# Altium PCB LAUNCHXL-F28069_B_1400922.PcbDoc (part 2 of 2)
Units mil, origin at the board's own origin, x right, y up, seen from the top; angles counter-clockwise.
Board outline 5140 x 2010 mil, 4 copper layers (Top, GND, VDD, Bottom), stack 60.63 mil thick; 212 components, 173 nets, 714 pads, 424 vias.
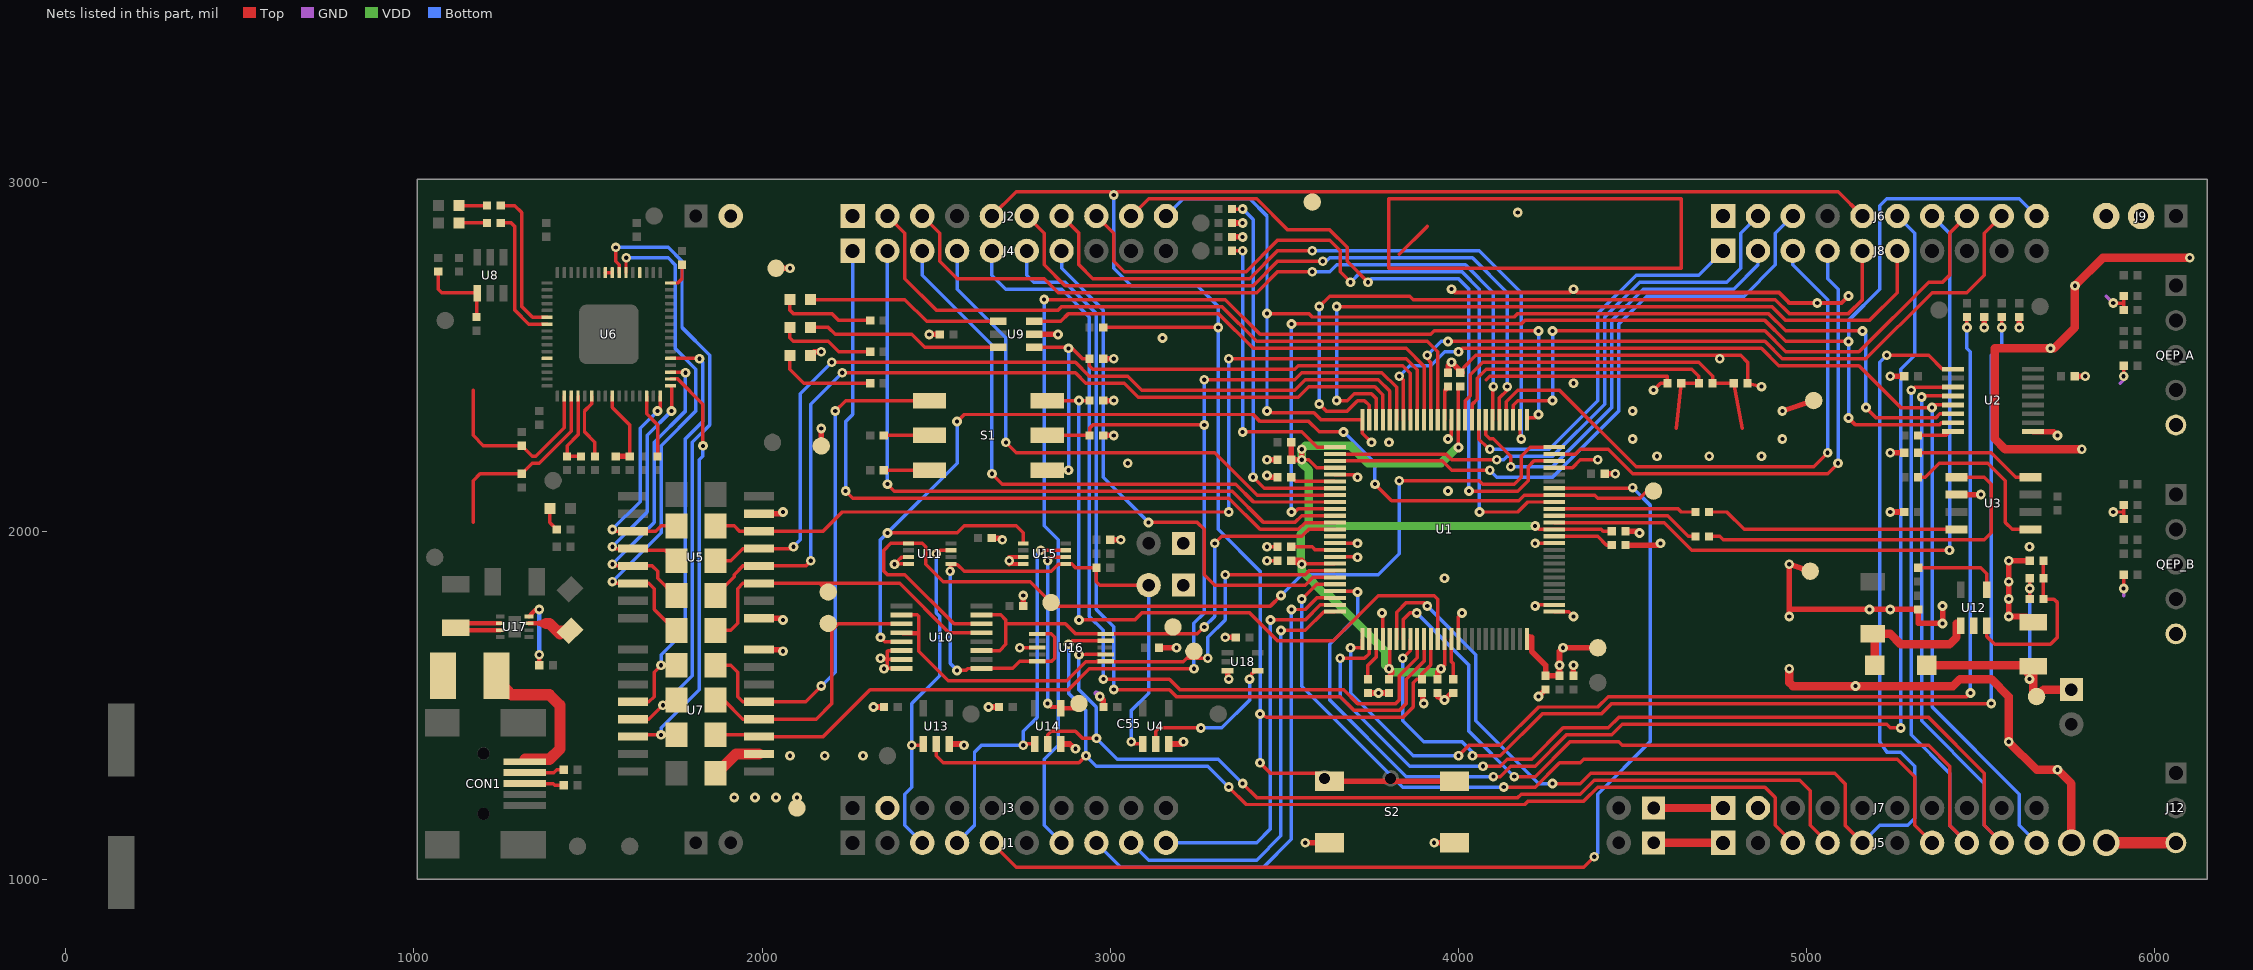
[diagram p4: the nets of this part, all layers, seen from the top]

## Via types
v1: diameter 28/28/28/28 (per signal layer), hole 12, Top to Bottom, 422 vias
v2: diameter 76.77/67.18/67.18/76.77 (per signal layer), hole 51.18, Top to Bottom, 2 vias

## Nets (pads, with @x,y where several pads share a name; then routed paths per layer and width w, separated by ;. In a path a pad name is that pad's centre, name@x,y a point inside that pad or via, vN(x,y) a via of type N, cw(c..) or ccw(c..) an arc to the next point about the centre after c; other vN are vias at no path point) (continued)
GND: C1.2 C2.2 C3.2 C4.2 C5.2 C6.2 C7.2 C8.2 C9.2 C19.2 C20.2 C21.2 C22.2 C23.2 C24.2 C26.2 C27.2 C28.2 C29.2 C30.2 C31.2 C32.2 C33.2 C34.2 C35.2 C36.2 C37.2 C38.2 C39.2 C40.2 C41.1 C42.2 C46.2 C47.2 C48.2 C49.2 C50.2 C51.2 C52.2 C53.2 C54.2 C55.2@5910.31,1875 D1.C J2.1 J3.2 J6.1 J7.2 J9.2 J9.3 JP2.2 JP6.1 JP7.1 QEP_A.5 QEP_B.5 R8.1 R9.1 R10.1 R25.2 R42.2 R45.2 S2.P$1 S2.P$2 TP20.TP TP21.TP TP22.TP TP23.TP TP24.TP U1.4 U1.15 U1.26 U1.27 U1.36 U1.47 U1.62 U1.80 U1.90 U1.92 U2.P$9 U3.P$2 U4.3 U5.9 U5.15 U7.2 U7.8 U9.2 U10.P$6 U10.P$7 U10.P$8 U11.P$3 U11.P$4 U12.2 U13.3 U14.3 U15.P$3 U15.P$4 U16.P$3 U18.3 | length 10150.3
  Top w10: v1(2340,1635) 2343.54,1631.46 2360,1631.46 ; v1(2350,1605) 2350.87,1605.87 v1@2360,1605.87 ; v1(2380,1905) v1@2390,1905.86 ; U10.P$8@2400,1605.87 v1@2360.87,1605.87 ; U10.P$7@2400,1631.46 2360,1631.46 ; U10.P$6@2400,1657.05 2362.05,1657.05 2360,1655 2360,1631.46 ; U11.P$4@2420,1905.94 2400.94,1905.94 ; U11.P$3@2420,1925.63 2400.63,1925.63 2390,1915 v1@2390,1905.86 ; v1(2710,1915) 2710.94,1914.06 v1@2710.94,1905.94 ; v1(2740,1665) 2740.63,1665.63 U16.P$3@2790,1665.63 ; v1(3450,1915) C30.2@3480.31,1915 ; v1(3450,1955) C6.2@3480.31,1955 ; U1.92@3645.04,1926.26 3708.74,1926.26 v1(3710,1925) ; U1.90@3645.04,1965.63 3709.37,1965.63 v1(3710,1965) ; U1.80@3645.04,2162.48 3702.52,2162.48 v1(3710,2155) ; v1(3780,1765) 3782.83,1762.17 U1.4@3782.83,1690.04 ; v1(3970,2265) 3979.69,2274.69 U1.62@3979.69,2319.96 ; v1(3980,2695) 3990,2685 ; U1.15@3999.37,1690.04 3999.37,1754.37 v1(4010,1765) ; C28.2@4005,2454.69 4015,2470 4050,2505 4810,2505 4830,2485 4830,2425 v1(4870,2415) ; 4080,2435 4090,2445 4600,2445 4600,2425.31 C4.2@4600.31,2425 4580,2425 v1(4560,2405) ; v1(4220,1785) 4223.46,1788.46 U1.27@4274.96,1788.46 ; v1(4220,1965) 4220.63,1965.63 U1.36@4274.96,1965.63 ; U1.26@4274.96,1768.78 4316.22,1768.78 v1(4330,1755) ; U1.47@4274.96,2182.17 4327.17,2182.17 4350,2205 v1(4400,2205) ; v1(5880,2055) 5910,2055 5910.32,2054.69 ; v1(5880,2655) 5910.32,2655 ; v1(5910,1835) 5910.32,1835.32 C55.2@5910.31,1875 ; v1(5910,2445) 5910.32,2445.31 C52.2@5910.31,2475 ; C54.2@5910.31,2035 5910.32,2054.69 ; C53.2@5910.31,2075 5910.32,2054.69 ; C51.2@5910.31,2635 5910.32,2655 ; C50.2@5910.31,2675 5910.32,2655 ; v1@2360,1605.87 2360,1631.46 ; v1@2360,1605.87 v1@2360.87,1605.87 ; v1@2360,1605.87 2360,1605 v1@2360.87,1605.87 ; v1@2390,1905.86 2390,1905 2400.94,1905.94 ; v1@2390,1905.86 2390.94,1905.94 2400.94,1905.94
  Top w12: U15.P$4@2750,1905.94 2710.94,1905.94 2710,1905 v1(2710,1915) 2710,1925 2710.63,1925.63 U15.P$3@2750,1925.63 ; 3990,2685 4320,2685 v1(4330,2695) 4340,2685 4920,2685 4950,2655 v1(5030,2655) 5100,2655 v1(5120,2675)
  Top w16: U7.8@1991.1,1660 2055,1660 v1(2060,1655) ; U5.9@1991.1,1750 2055,1750 v1(2060,1745) ; U5.15@1991.1,2050 2055,2050 v1(2060,2055) ; TP22.TP@2040,2755 v1(2080,2755) ; TP21.TP@2100,1205 v1(2100,1235) ; D1.C@2139.53,2505 2140,2505 2150,2515 v1(2170,2515) ; TP20.TP@2170,2245 v1(2170,2295) ; v1(2320,1495) C46.2@2350.31,1495 ; v1(2480,2565) C24.2@2510.31,2565 ; U13.3@2537.4,1388.82 2576.18,1388.82 v1(2580,1385) ; v1(2650,1495) C47.2@2680.31,1495 ; C48.2@2659.69,1980 2685,1980 v1(2690,1975) ; C38.2@2749.69,1785 2749.69,1814.69 v1(2750,1815) ; U9.2@2781.18,2565 v1(2850,2565) ; U14.3@2857.4,1388.82 2883.82,1388.82 v1(2900,1375) ; v1(2970,1525) 2980.32,1514.69 C7.2@2980.31,1495 ; R9.1@2979.69,2275 2999.69,2275.31 v1(3010,2275) ; R10.1@2979.69,2375 3009.69,2375.31 v1(3010,2375) ; R8.1@2979.69,2495 v1(3010,2495) ; C49.2@2999.69,1975 v1(3030,1975) ; C42.2@3139.69,1665 v1(3190,1665) ; U4.3@3167.4,1388.82 3203.82,1388.82 v1(3210,1395) ; v1(3330,1695) 3350.32,1695.32 C9.2@3360.31,1695 ; U18.3@3336.69,1599.41 3336.69,1578.31 v1(3340,1575) ; C33.2@3349.69,2845 v1(3380,2845) ; C36.2@3349.69,2885 v1(3380,2885) ; v1(3450,2160) 3450,2155 C5.2@3480.31,2155 ; v1(3450,2205) C29.2@3480.31,2205 ; v1(3560,1105) S2.P$1@3630,1105 ; C1.2@3740,1535.31 C20.2@3799.69,1535.32 ; v1(3770,1535) C20.2@3799.69,1535.32 ; C20.2@3800,1535.31 C20.2@3799.69,1535.32 ; C39.2@3895,1535.31 v1(3900,1505) ; v1(3930,1105) S2.P$2@3989,1105 ; C26.2@3940,1535.31 3940,1525 v1(3960,1515) 3980,1535 C2.2@3985,1535.31 ; C23.2@3970,2454.69 3970,2475 v1(3980,2485) 4005,2460 C28.2@4005,2454.69 4009.69,2454.69 C28.2@4010,2455 ; v1(4230,1525) C19.2@4250,1545.31 ; C21.2@4330,1584.69 v1(4330,1615) ; C40.2@4419.69,2165 v1(4450,2165) ; C22.2@4479.69,1960 4575,1960 v1(4580,1965) ; C27.2@4479.69,2000 4515,2000 v1(4520,1995) ; v1(4930,2345) TP24.TP@5020,2375 ; v1(4950,1755) 4950,1775 ; TP23.TP@5010,1885 v1(4950,1905) 4950,1775 ; v1(5240,2055) C37.2@5280.31,2055 ; v1(5240,2225) R42.2@5280.31,2225 ; v1(5240,2445) C31.2@5280.31,2445 ; v1(5390,1785) v1(5390,1735) 5320,1735 C8.2@5320,1775.31 5099.69,1775.32 4950,1775 ; U3.P$2@5430,2105 v1(5500,2105) ; v1(5510,2585) C34.2@5510,2615.31 ; v1(5610,2585) C35.2@5610,2615.31 ; R45.2@5640.31,1915 v1(5580,1915) v1(5580,1855) v1(5580,1805) v1(5580,1755) 5630,1755 C41.1@5650,1735 ; U2.P$9@5650.32,2285.87 5709.13,2285.87 v1(5720,2275) ; C32.2@5769.69,2445 v1(5800,2445)
  Top w24: v1(4950,1605) 4950,1565 4960,1555 v1(5140,1555) 5420,1555 5440,1575 5530,1575 5580,1525 v1(5580,1395) 5660,1315 v1(5720,1315) 5760,1275 v2(5760,1105) ; v1(5790,2235) 5570,2235 5540,2265 5540,2525 v1(5700,2525) 5710,2525 5770,2585 v1(5770,2705) 5850,2785 v1(6100,2785)
  Top w32: R25.2@1865.98,1305 1870,1305 1925,1360 U7.2@1991.1,1360
  GND w10: 5860,2675 v1(5880,2655) ; v1@5880,2045 v1(5880,2055) ; 5900,2425 5910,2435 v1(5910,2445) ; 5910,1815 v1(5910,1835)
  GND w16: 2960,1535 v1(2970,1525)
  other v1: 1920,1235 1980,1235 2040,1235 2080,1355 2180,1355 2290,1355 5180,1775 5240,1775 3960,1865 5640,1955 3970,2115 3050,2195 4570,2215 4720,2215 4870,2215 3800,2255 4500,2265 4930,2265 4500,2345 4330,2425 4750,2495 3150,2555 4170,2915
GPIO0: J4.1 U1.87 | length 2157
  Top w10: v1(2240,2115) 2260,2095 3340,2095 3430,2005 3540,2005 3559.69,2024.69 U1.87@3645.04,2024.69
  Bottom w10: v1(2240,2115) 2240,2315 2260,2335 J4.1@2260,2805
GPIO1: J4.2 U1.86 | length 2008.6
  Top w10: v1(2360,2135) 2380,2115 3350,2115 3440,2025 3530,2025 3549.37,2044.37 U1.86@3645.04,2044.37
  Bottom w10: v1(2360,2135) J4.2@2360,2805
GPIO2: J4.3 U1.84 | length 1741.5
  Top w10: v1(2660,2165) 2690,2135 3360,2135 3411.26,2083.74 U1.84@3645.04,2083.74
  Bottom w10: J4.3@2460,2805 2460,2735 2660,2535 v1(2660,2165)
GPIO3: J4.4 U1.83 | length 1615.8
  Top w10: v1(2700,2255) 2730,2225 3300,2225 3421.57,2103.43 U1.83@3645.04,2103.43
  Bottom w10: J4.4@2560,2805 2560,2695 2700,2555 v1(2700,2255)
GPIO4: J4.5 U1.9 | length 2535.7
  Top w10: v1(2980,1575) 3170,1575 3200,1545 3670,1545 3710,1505 3820,1505 3830,1515 3830,1585 3881.26,1636.26 U1.9@3881.26,1690.04
  Bottom w10: J4.5@2660,2805 2660,2735 2700,2695 2860,2695 2940,2615 2940,1755 2980,1715 v1(2980,1575)
GPIO5: J4.6 U1.10 | length 2495.6
  Top w10: v1(3010,1545) 3170,1545 3190,1525 3660,1525 3700,1485 3830,1485 3850,1505 3850,1575 3900.94,1625.94 U1.10@3900.94,1690.04
  Bottom w10: J4.6@2760,2805 2760,2735 2780,2715 2870,2715 2960,2625 2960,1775 3010,1725 v1(3010,1545)
GPIO6: J8.1 U1.58 | length 1151.6
  Top w10: U1.58@4058.43,2319.96 4058.43,2263.43 4063.43,2258.43 v1(4090,2235)
  Bottom w10: v1(4090,2235) 4260,2235 4400,2375 4400,2625 4510,2735 4690,2735 J8.1@4760,2805
GPIO7: J8.2 U1.57 | length 1307.3
  Top w10: U1.57@4078.11,2319.96 4078.11,2276.89 4090,2265 4100,2265 4150,2215 v1(4150,2185)
  Bottom w10: v1(4150,2185) 4270,2185 4440,2355 4440,2605 4530,2695 4790,2695 4860,2765 J8.2@4860,2805
GPIO8: J8.3 U1.54 | length 1717.8
  Top w10: U1.54@4137.17,2319.96 4137.17,2372.17 4170,2405 4290,2405 4510,2185 5020,2185 v1(5060,2225)
  Bottom w10: J8.3@4960,2805 4960,2765 5060,2665 v1(5060,2225)
GPIO9: J8.4 U1.49 | length 1484.5
  Top w10: U1.49@4274.96,2221.54 4336.54,2221.54 4350,2235 4430,2235 4500,2165 5060,2165 v1(5090,2195)
  Bottom w10: J8.4@5060,2805 5060,2725 5090,2695 v1(5090,2195)
GPIO10: J8.5 U1.74 | length 2241
  Top w10: v1(3600,2365) 3620,2345 3680,2345 3710,2375 3730,2375 3743.46,2361.54 U1.74@3743.46,2319.96 ; v1(3600,2645) 3630,2675 3860,2675 3870,2665 4910,2665 4950,2625 5120,2625 5160,2665 J8.5@5160,2805
  Bottom w10: v1(3600,2365) v1(3600,2645)
GPIO11: J8.6 U1.73 | length 2238.5
  Top w10: v1(3650,2375) 3680,2375 3700,2395 3750,2395 3763.15,2381.85 U1.73@3763.15,2319.96 ; v1(3650,2645) 4900,2645 4940,2605 5180,2605 5260,2685 J8.6@5260,2805
  Bottom w10: v1(3650,2375) v1(3650,2645)
GPIO12: J1.5 U1.44 | length 3144.2
  Top w10: J1.5@2660,1105 2730,1035 4360,1035 v1(4390,1065) ; U1.44@4274.96,2123.11 4498.11,2123.11 v1(4500,2125)
  Bottom w10: v1(4390,1065) 4400,1075 4400,1245 4550,1395 4550,2075 v1(4500,2125)
GPIO13: J4.7 U1.95 | length 1578.5
  Top w10: v1(3110,2025) 3250,2025 3270,2005 3270,1875 3300,1845 3560,1845 3582.2,1867.2 U1.95@3645.04,1867.2
  Bottom w10: J4.7@2860,2805 2860,2755 2980,2635 2980,2155 v1(3110,2025)
GPIO14: J5.7 U1.96 | length 2507.3
  Top w10: v1(3550,1805) 3592.52,1847.52 U1.96@3645.04,1847.52 ; v1(4130,1265) 4220,1265 4290,1335 4350,1335 4360,1345 5260,1345 5310,1295 5310,1155 J5.7@5360,1105
  Bottom w10: v1(3550,1805) 3550,1555 3840,1265 v1(4130,1265)
GPIO15: TP28.TP U1.88 U10.P$11 U10.P$15 U16.P$10 | length 1451.7
  Top w10: U10.P$11@2630.32,1657.05 2682.05,1657.05 2700,1675 2700,1735 ; U10.P$15@2630.32,1759.41 2685.59,1759.41 2700,1745 2700,1735 ; TP28.TP@3180,1725 3180,1715 TP28.TP@3170,1705 ; v1(3270,1725) 3250,1705 TP28.TP@3170,1705 ; v1(3300,1965) 3320,1985 3550,1985 3570,2005 U1.88@3645.04,2005 ; 2700,1735 2701.18,1733.82 2871.18,1733.82 2900,1705 U16.P$10@2986.85,1705 TP28.TP@3170,1705
  Bottom w10: v1(3270,1725) 3300,1755 v1(3300,1965)
GPIO16: J2.6 U1.55 | length 1964.5
  Top w10: J2.6@2760,2905 2810,2855 2810,2765 2870,2705 3410,2705 3480,2775 v1(3610,2775) ; U1.55@4117.48,2319.96 4117.48,2382.48 4140,2405 v1(4140,2415)
  Bottom w10: v1(3610,2775) 3620,2775 3630,2785 4040,2785 4140,2685 v1(4140,2415)
GPIO17: J2.7 U1.52 | length 2008.7
  Top w10: J2.7@2860,2905 2910,2855 2910,2765 2950,2725 3400,2725 3480,2805 v1(3580,2805) ; U1.52@4176.54,2319.96 4176.54,2268.46 v1(4180,2265) v1@4181.54,2266.54
  Bottom w10: v1(3580,2805) 4060,2805 4180,2685 v1(4180,2265)
GPIO18: J1.7 U1.51 | length 3366.8
  Top w10: v1(2810,2665) 3330,2665 3430,2565 3920,2565 3930,2575 v1(4230,2575) ; U1.51@4200,2325 4196.22,2321.22 U1.51@4196.22,2319.96 4201.22,2324.96 4201.22,2326.22 4221.22,2326.22 v1(4230,2335)
  Bottom w10: v1(2810,2665) 2810,2015 2850,1975 2850,1385 2810,1345 2810,1155 J1.7@2860,1105 ; v1(4230,2335) v1(4230,2575)
GPIO19: J2.2 U1.64 | length 2021.2
  Top w10: J2.2@2360,2905 2410,2855 2410,2725 2500,2635 2850,2635 2860,2645 3320,2645 3420,2545 3910,2545 3940.32,2514.69 U1.64@3940.31,2319.96
GPIO20: J5.5 U1.6 U2.P$1 | length 3705.2
  Top w10: U1.6@3822.2,1690.04 3822.2,1767.2 3850,1795 3900,1795 v1(3910,1785) ; v1(4270,1275) 4350,1275 4380,1305 5080,1305 5110,1275 5110,1155 J5.5@5160,1105 ; v1(5230,2505) 5350,2505 5390,2465 U2.P$1@5420,2465
  Bottom w10: v1(3910,1785) 4050,1645 4050,1455 4230,1275 v1(4270,1275) ; J5.5@5160,1105 5210,1155 5290,1155 5310,1175 5310,1325 5270,1365 5230,1365 5210,1395 5210,2485 v1(5230,2505)
GPIO21: J5.8 U1.7 U2.P$3 | length 3738.9
  Top w10: U1.7@3841.89,1690.04 3841.89,1746.89 3860,1765 v1(3880,1765) ; v1(4160,1295) 4220,1295 4320,1395 4460,1395 4470,1385 5350,1385 5410,1325 5410,1155 J5.8@5460,1105 ; v1(5300,2405) 5311.18,2413.82 U2.P$3@5420,2413.82
  Bottom w10: v1(3880,1765) 4030,1615 4030,1425 v1(4160,1295) ; v1(5300,2405) 5300,1415 5410,1305 5410,1155 J5.8@5460,1105
GPIO22: J1.8 U1.98 | length 1420.9
  Top w10: v1(3520,1775) 3560,1775 3593.15,1808.15 U1.98@3645.04,1808.15
  Bottom w10: J1.8@2960,1105 3030,1035 3440,1035 3520,1115 v1(3520,1775)
GPIO23: J5.9 U1.2 U2.P$4 | length 3984.1
  Top w10: v1(3660,1635) 3730,1635 3743.46,1648.46 U1.2@3743.46,1690.04 ; v1(4070,1325) 4120,1325 4140,1345 4210,1345 4300,1435 4430,1435 4460,1465 5350,1465 5510,1305 5510,1155 J5.9@5560,1105 ; v1(5330,2385) 5343.23,2388.23 U2.P$4@5420,2388.23
  Bottom w10: v1(3660,1635) 3660,1525 3860,1325 v1(4070,1325) ; v1(5330,2385) 5330,1455 5510,1275 5510,1155 J5.9@5560,1105
GPIO24: J6.6 U1.97 | length 3713.9
  Top w10: U1.97@3645.04,1827.83 3707.17,1827.83 v1(3710,1825) ; v1(4100,1295) 4120,1295 4150,1325 4220,1325 4310,1415 4440,1415 4470,1445 5230,1445 5240,1435 v1(5270,1435)
  Bottom w10: v1(3710,1825) 3710,1755 3630,1675 3630,1515 3850,1295 v1(4100,1295) ; J6.6@5260,2905 5310,2855 5310,2505 5270,2465 v1(5270,1435)
GPIO25: J6.7 U1.39 | length 2148.8
  Top w10: U1.39@4274.96,2024.69 4590.32,2024.69 4670,1945 v1(5410,1945)
  Bottom w10: J6.7@5360,2905 5410,2855 v1(5410,1945)
GPIO26: J6.3 U1.78 | length 1844.2
  Top w10: U1.78@3645.04,2201.85 3953.15,2201.85 3980,2175 v1(4090,2175)
  Bottom w10: v1(4090,2175) 4110,2155 4270,2155 4460,2345 4460,2595 4540,2675 4820,2675 4910,2765 4910,2855 J6.3@4960,2905
GPIO27: J6.2 U1.77 | length 1716.8
  Top w10: U1.77@3645.04,2221.54 3963.46,2221.54 3980,2205 v1(4110,2205)
  Bottom w10: v1(4110,2205) 4130,2205 4140,2215 4270,2215 4420,2365 4420,2615 4520,2715 4770,2715 4810,2755 4810,2855 J6.2@4860,2905
GPIO28: TP9.TP U1.50 U10.P$14 U11.P$1 | length 2835.4
  Top w10: U10.P$14@2630.32,1733.82 2551.18,1733.82 2410,1875 2360,1875 2350,1885 2350,1945 2370,1965 U11.P$1@2420,1965 2460,1965 2470,1955 2470,1905 2520,1855 2770,1855 2820,1805 TP9.TP@2820,1785 ; v1(3490,1815) 3460,1785 TP9.TP@2840,1785 ; v1(3830,2145) 4060,2145 4070,2135 4160,2135 4180,2155 4180,2215 4206.22,2241.22 U1.50@4274.96,2241.22 ; TP9.TP@2820,1785 TP9.TP@2830,1795 TP9.TP@2840,1785 ; TP9.TP@2820,1785 TP9.TP@2840,1785
  Bottom w10: v1(3490,1815) 3550,1875 3770,1875 3830,1935 v1(3830,2145)
GPIO29: TP27.TP U1.43 U10.P$5 U15.P$1 | length 3377.2
  Top w10: v1(2340,1695) 2352.36,1682.64 U10.P$5@2400,1682.64 ; v1(2360,1995) 2560,1995 2580,2015 2730,2015 2750,1995 U15.P$1@2750,1965 ; v1(2560,2315) 2580,2335 3410,2335 3430,2315 3570,2315 3600,2285 v1(3670,2285) ; v1(3760,2135) 3807.56,2087.44 4172.44,2087.44 4188.43,2103.43 U1.43@4274.96,2103.43 4391.57,2103.43 4400,2095 4520,2095 4540,2115 TP27.TP@4560,2115
  Bottom w10: v1(2340,1695) 2340,1975 v1(2360,1995) 2560,2195 v1(2560,2315) ; v1(3670,2285) 3760,2195 v1(3760,2135)
GPIO30: R44.2 U1.41 | length 409.5
  Top w10: U1.41@4274.96,2064.06 4599.06,2064.06 4630,2065 4640,2055 R44.2@4680.31,2055
GPIO31: R43.2 U1.40 | length 430
  Top w10: U1.40@4274.96,2044.37 4600.63,2044.37 4660,1985 R43.2@4680.31,1985
GPIO32: J1.10 U1.99 | length 1119.6
  Top w10: v1(3460,1745) 3560,1745 3603.46,1788.46 U1.99@3645.04,1788.46
  Bottom w10: J1.10@3160,1105 3420,1105 3460,1145 v1(3460,1745)
GPIO33: J1.9 U1.100 | length 1247
  Top w10: v1(3490,1715) 3560,1715 3613.78,1768.78 U1.100@3645.04,1768.78
  Bottom w10: J1.9@3060,1105 3110,1055 3420,1055 3490,1125 v1(3490,1715)
GPIO34: R8.2 S1.1 U1.68 U9.1 | length 1674.9
  Top w10: U9.1@2781.18,2527.6 2867.4,2527.6 v1(2880,2525) 2890,2525 2920,2495 R8.2@2940.31,2495 2940,2494.69 2940,2475 2950,2465 3530,2465 3540,2475 3840,2475 3861.57,2453.43 U1.68@3861.57,2319.96 ; S1.1@2819.29,2175 v1(2880,2175)
  Bottom w10: v1(2880,2175) v1(2880,2525)
GPIO39: U1.66 U9.3 | length 1345.7
  Top w10: U9.3@2781.18,2602.4 2857.4,2602.4 2880,2625 3310,2625 3410,2525 3850,2525 3900.94,2474.06 U1.66@3900.94,2319.96
GPIO40: R36.1 U1.82 | length 1061
  Top w10: R36.1@3349.69,2925 v1(3380,2925) ; v1(3410,2155) 3441.89,2123.11 U1.82@3645.04,2123.11
  Bottom w10: v1(3380,2925) 3410,2895 v1(3410,2155)
GPIO41: R37.1 U1.76 | length 833.5
  Top w10: R37.1@3349.69,2805 v1(3380,2805) ; v1(3380,2285) 3550,2285 3593.78,2241.22 U1.76@3645.04,2241.22
  Bottom w10: v1(3380,2285) v1(3380,2805)
GPIO42: R40.1 U1.1 | length 3200.2
  Top w10: v1(3690,1665) 3720,1665 3723.78,1668.78 U1.1@3723.78,1690.04 ; v1(4000,1355) 4030,1385 4120,1385 4230,1495 4400,1495 4430,1525 5460,1525 v1(5470,1535) ; v1(5460,2585) R40.1@5460,2615.31
  Bottom w10: v1(3690,1665) 3690,1535 3870,1355 v1(4000,1355) ; v1(5460,2585) 5460,2525 5470,2515 v1(5470,1535)
GPIO43: R41.1 U1.8 | length 3166.1
  Top w10: v1(3840,1635) 3861.57,1656.57 U1.8@3861.57,1690.04 ; v1(4040,1355) 4120,1355 4240,1475 4410,1475 4440,1505 v1(5530,1505) ; v1(5560,2585) R41.1@5560,2615.31
  Bottom w10: v1(3840,1635) 3840,1455 3900,1395 4010,1395 4040,1365 v1(4040,1355) ; v1(5530,1505) 5530,2505 5560,2535 v1(5560,2585)
GPIO44: J2.3 U1.56 | length 2209.5
  Top w10: J2.3@2460,2905 2510,2855 2510,2775 2560,2725 2810,2725 2850,2685 3420,2685 3480,2745 v1(3580,2745) ; U1.56@4097.8,2319.96 4097.8,2402.8 v1(4100,2415)
  Bottom w10: v1(3580,2745) 3630,2745 3650,2765 4020,2765 4100,2685 v1(4100,2415)
GPIO50: J2.8 U1.42 | length 2235.3
  Top w10: J2.8@2960,2905 3010,2855 3010,2775 3040,2745 3390,2745 3480,2835 3630,2835 3660,2805 3660,2745 v1(3690,2715) ; v1(4060,2055) 4170,2055 4198.74,2083.74 U1.42@4274.96,2083.74
  Bottom w10: v1(3690,2715) 3720,2745 4010,2745 4060,2695 v1(4060,2055)
GPIO51: J2.9 U1.48 | length 2014.5
  Top w10: J2.9@3060,2905 3110,2955 3420,2955 3510,2865 3630,2865 3680,2815 3680,2775 v1(3740,2715) ; v1(4030,2115) 4170,2115 4200,2145 4200,2185 4216.85,2201.85 U1.48@4274.96,2201.85
  Bottom w10: v1(3740,2715) 3750,2725 4000,2725 4030,2695 v1(4030,2115)
GPIO52: J6.8 U1.53 | length 1807.2
  Top w10: U1.53@4156.85,2319.96 4156.85,2361.85 4170,2375 v1(4270,2375) ; v1(4270,2575) 4880,2575 4940,2515 5150,2515 5350,2715 5390,2715 5410,2735 5410,2855 J6.8@5460,2905
  Bottom w10: v1(4270,2375) v1(4270,2575)
GPIO53: J6.9 U1.65 | length 2116.8
  Top w10: v1(3910,2505) 3910,2495 3920.63,2484.37 U1.65@3920.63,2319.96 ; v1(3970,2545) 4880,2545 4930,2495 5170,2495 5360,2685 5460,2685 5510,2735 5510,2855 J6.9@5560,2905
  Bottom w10: v1(3910,2505) 3950,2545 v1(3970,2545)
GPIO54: J5.10 U1.69 U2.P$5 | length 3200.9
  Top w10: v1(3830,2445) 3841.89,2433.11 U1.69@3841.89,2319.96 ; v1(4000,2515) 4010,2525 4870,2525 4920,2475 5150,2475 5270,2355 v1(5360,2355) 5367.64,2362.64 U2.P$5@5420,2362.64
  Bottom w10: v1(3830,2445) 3860,2475 3920,2475 3960,2515 v1(4000,2515) ; v1(5360,2355) 5360,1495 5610,1245 5610,1155 J5.10@5660,1105
GPIO55: J2.10 U1.75 U2.P$6 | length 3480.7
  Top w10: v1(3450,2345) 3464.96,2340.04 3584.96,2340.04 3605,2320 U1.75@3723.78,2319.96 3723.78,2281.22 v1(3750,2255) ; v1(3450,2625) 3570,2625 3580,2615 4160,2615 4170,2625 4890,2625 4940,2575 v1(5160,2575) ; v1(5170,2355) 5200,2325 5370,2325 5382.05,2337.05 U2.P$6@5420,2337.05
  Bottom w10: J2.10@3160,2905 3210,2955 3400,2955 3450,2905 v1(3450,2625) v1(3450,2345) ; v1(5160,2575) 5170,2565 v1(5170,2355)
GPIO56: J6.10 U1.85 U2.P$7 | length 3735
  Top w10: v1(3520,2055) 3530,2055 3539.06,2064.06 U1.85@3645.04,2064.06 ; v1(3520,2595) 4180,2595 4190,2605 4880,2605 4940,2545 v1(5120,2545) ; v1(5120,2325) 5140,2305 5380,2305 5386.46,2311.46 U2.P$7@5420,2311.46
  Bottom w10: v1(3520,2055) v1(3520,2595) ; v1(5120,2325) v1(5120,2545) 5120,2605 5210,2695 5210,2935 5230,2955 5610,2955 J6.10@5660,2905
GPIO57: U1.89
GPIO58: TP29.TP U1.94 U10.P$2 U10.P$4 U16.P$6 | length 1812.5
  Top w10: U10.P$2@2400,1759.41 2445.59,1759.41 2450,1755 2450,1705 ; U16.P$6@2986.85,1626.26 2961.26,1626.26 2930,1625 ; TP29.TP@3240,1655 3220,1635 ; v1(3280,1635) 3220,1635 ; v1(3330,1875) 3560,1875 3571.89,1886.89 U1.94@3645.04,1886.89 ; 2450,1705 2403.23,1705 U10.P$4@2400,1708.23 2446.77,1708.23 2450,1705 ; 2450,1705 2450,1655 2535,1570 2875,1570 2930,1625 ; 2930,1625 3210,1625 3220,1635
  Bottom w10: v1(3280,1635) 3280,1695 3330,1745 v1(3330,1875)
J1.3: J1.3 U11.P$7 U13.1 | length 976.8
  Top w10: v1(2430,1385) 2458.78,1385 U13.1@2462.6,1388.82 ; v1(2500,1935) 2510.31,1945.32 U11.P$7@2542.05,1945.31
  Bottom w10: J1.3@2460,1105 2410,1155 2410,1245 2430,1265 v1(2430,1385) 2430,1505 2510,1585 2510,1755 2500,1765 v1(2500,1935)
J1.4: J1.4 U14.1 U15.P$7 | length 1115.6
  Top w10: v1(2750,1385) 2756.18,1388.82 U14.1@2782.6,1388.82 ; v1(2800,1945) 2871.73,1945 U15.P$7@2872.05,1945.31
  Bottom w10: J1.4@2560,1105 2610,1155 2610,1365 2630,1385 v1(2750,1385) 2750,1425 2790,1465 2790,1935 v1(2800,1945)
J7.3: J5.3 U13.2 U16.P$9 | length 3154.1
  Top w10: U13.2@2500,1388.82 2500,1355 2520,1335 2910,1335 v1(2930,1355) ; v1(2880,1675) 2890.32,1685.32 U16.P$9@2986.85,1685.31 ; v1(3340,1265) 3390,1215 4190,1215 4200,1225 4360,1225 4400,1265 4880,1265 4910,1235 4910,1155 J5.3@4960,1105
  Bottom w10: v1(2880,1675) 2880,1535 2930,1485 v1(2930,1355) 2960,1325 3280,1325 v1(3340,1265)
J7.4: J5.4 U14.2 U16.P$7 | length 2840.5
  Top w10: U14.2@2820,1388.82 2820,1415 2830,1425 2900,1425 2920,1405 v1(2960,1405) ; v1(2910,1645) 2929.06,1645.94 U16.P$7@2986.85,1645.94 ; v1(3380,1275) 3420,1235 4170,1235 4180,1245 4350,1245 4390,1285 4980,1285 5010,1255 5010,1155 J5.4@5060,1105
  Bottom w10: v1(2910,1645) 2910,1545 2960,1495 v1(2960,1405) 3020,1345 3310,1345 v1(3380,1275)
JTAG_TRST: R28.2 S1.4 U7.5 | length 1496.9
  Top w10: R28.2@1865.98,1615 1910,1615 1930,1595 1930,1525 1945,1510 U7.5@1991.1,1510 2125,1510 v1(2170,1555) ; v1(2210,2345) 2240,2375 S1.4@2480.71,2375
  Bottom w10: v1(2170,1555) 2210,1595 v1(2210,2345)
LP_5V: C25.1 C41.2 D3.C JP3.1 R17.1 TP2.TP | length 993.5
  Top w10: v1@5640,1585 5650,1595 C41.2@5650,1612.01 C41.2@5650,1615 ; C25.1@5640.31,1805 v1(5640.32,1835) R17.1@5640.31,1865
  Top w16: C41.2@5642.99,1605 C41.2@5650,1612.01
  Top w24: D3.C@5344.8,1615 C41.2@5620,1615 ; JP3.1@5760,1545 5680,1545 TP2.TP@5660,1525 5650,1532.01 C41.2@5650,1612.01 5650,1585 v1(5640,1575) 5640,1585 C41.2@5620,1615 ; C41.2@5620,1615 5640,1605 5650,1615 C41.2@5620,1615
  Bottom w10: v1(5640,1575) 5640,1825.32 v1(5640.32,1835)
MUX_SEL: JP7.2 R11.2 U4.1 U10.P$9 U11.P$5 U15.P$5 U16.P$1 U16.P$5 | length 1883.3
  Top w10: U11.P$5@2542.05,1905.94 2542.05,1887.05 v1(2540,1885) 2540,1903.9 2561.1,1903.9 2580,1885 2830,1885 2850,1905 2871.1,1905 U15.P$5@2872.05,1905.94 2889.06,1905.94 2900,1895 2960,1895 2960,1855 2970,1845 JP7.2@3110,1845 ; v1(2560,1600) 2585.87,1600.87 2590,1605 U10.P$9@2630.32,1605.87 2719.61,1605.87 2740,1626.26 U16.P$5@2790,1626.26 2831.26,1626.26 2840,1635 2840,1695 2830,1705 U16.P$1@2790,1705 ; v1(3060,1395) 3066.18,1388.82 U4.1@3092.6,1388.82
  Top w16: R11.2@2960,1895 R11.2@2960.31,1895
  Bottom w10: v1(2540,1885) 2540,1620 v1(2560,1600) ; v1(3060,1395) 3060,1485 3110,1535 JP7.2@3110,1845
N$1: R20.1 U5.3 U6.P$16 | length 632.1
  Top w10: v1(1570,2005) 1575,2000 U5.3@1628.9,2000 1695,2000 1710,2015 R20.1@1754.02,2015 ; v1(1700,2345) 1707.64,2352.64 U6.P$16@1707.64,2387.83
  Bottom w10: v1(1570,2005) 1650,2085 1650,2295 v1(1700,2345)
N$2: C17.1 U6.P$2 | length 541.7
  Top w10: 1170,2405 1170,2275 1199.69,2245.31 C17.1@1310,2245.31 1340.32,2215 1350,2215 1432.05,2297.05 U6.P$2@1432.05,2387.83
N$3: 
N$4: R19.1 U5.4 U6.P$17 | length 740.3
  Top w10: v1(1570,1955) 1575,1950 U5.4@1628.9,1950 1628.9,1953.9 1630,1955 1640,1945 1720,1945 1750,1915 R19.1@1754.02,1915 ; U6.P$17@1737.17,2417.36 1740,2410.2 v1(1740,2345)
  Bottom w10: v1(1570,1955) 1670,2055 1670,2275 v1(1740,2345)
N$5: R32.1 U6.P$18 U7.14 | length 1293.6
  Top w10: U7.14@1628.9,1410 1633.9,1415 R32.1@1754.02,1415 v1(1710,1415) ; U6.P$18@1737.17,2437.05 1757.95,2437.05 1830,2365 v1(1830,2245)
  Bottom w10: v1(1710,1415) 1710,1435 1820,1545 1820,2205 1830,2215 v1(1830,2245)
N$6: R18.1 U5.5 U6.P$19 | length 913.5
  Top w10: v1(1570,1905) 1575,1900 U5.5@1628.9,1900 1685,1900 1700,1885 1700,1865 1750,1815 R18.1@1754.02,1815 ; U6.P$19@1737.17,2456.73 1778.27,2456.73 v1(1780,2455)
  Bottom w10: v1(1570,1905) 1690,2025 1690,2255 1780,2345 v1(1780,2455)
N$7: C18.1 U6.P$3 | length 561.8
  Top w10: 1170,2025 1170,2145 1190,2165 1309.69,2165 C18.1@1310,2164.69 1340.32,2195 1360,2195 1451.73,2286.73 U6.P$3@1451.73,2387.83
N$8: C3.1 R7.2 U1.60 | length 1076.3
  Top w10: U1.60@4019.06,2319.96 4019.06,2374.06 4034.06,2389.06 4034.06,2449.06 4070,2485 4690,2485 4730,2445 4730,2445.31 R7.2@4729.69,2425 C3.1@4790.31,2425 4815,2295
N$9: R4.1 S1.6 | length 131
  Top w10: R4.1@2349.69,2175 S1.6@2480.71,2175
N$10: R5.1 S1.5 | length 131
  Top w10: R5.1@2349.69,2275 S1.5@2480.71,2275
N$11: C4.1 R7.1 U1.59 | length 981.9
  Top w10: U1.59@4038.74,2319.96 4038.74,2363.74 4053.74,2378.74 4053.74,2438.74 4080,2465 4670,2465 4690,2445 R7.1@4690,2425 ; 4625,2295 C4.1@4639.69,2425 R7.1@4690,2425 ; R7.1@4690.31,2425 R7.1@4690,2425
N$12: R12.2 R31.1 U8.1 | length 237.8
  Top w10: R12.2@1070,2745.31 1070,2695 1080,2685 1181.42,2685 U8.1@1182.6,2683.82 1180,2681.22 R31.1@1180,2614.69
N$13: R28.1 U6.P$21 U7.12 | length 1226.8
  Top w10: U7.12@1628.9,1510 1675,1510 1690,1525 1690,1595 v1(1710,1615) R28.1@1754.02,1615 ; U6.P$21@1737.17,2496.1 1818.9,2496.1 v1(1820,2495)
  Bottom w10: v1(1710,1615) 1710,1645 1780,1715 1780,2265 1830,2315 1830,2485 v1(1820,2495)
N$14: R23.1 U6.P$32 | length 78.3
  Top w10: U6.P$32@1737.17,2712.64 1757.64,2712.64 1770,2725 R23.1@1770,2765.31
N$15: U6.P$40 U6.P$41 | length 19.7
  Top w10: U6.P$41@1550.16,2742.17 U6.P$40@1569.84,2742.17
N$16: R16.1 U5.6 U6.P$38 | length 1502.6
  Top w10: v1(1570,1855) 1575,1850 U5.6@1628.9,1850 1675,1850 1690,1835 1690,1775 1740,1725 1750,1715 R16.1@1754.02,1715 ; U6.P$38@1609.21,2742.17 1609.21,2774.21 v1(1610,2785)
  Bottom w10: v1(1570,1855) 1710,1995 1710,2245 1810,2345 1810,2465 1750,2525 1750,2765 1730,2785 v1(1610,2785)
N$17: R24.2 U6.P$6 | length 194.2
  Top w10: U6.P$6@1510.79,2387.83 1510.79,2365.79 1490,2345 1490,2285 1520,2255 R24.2@1520,2215
  Top w16: R24.2@1520,2214.69 R24.2@1520,2215
N$18: J12.3 | length 200
  Top w32: v2(5860,1105) J12.3@6060,1105
N$19: R26.1 U6.P$54 | length 424.2
  Top w10: R26.1@1249.69,2935 1290,2935 1310,2915 1310,2645 1340.79,2614.21 U6.P$54@1382.83,2614.21
N$20: C11.1 L1.2 U6.P$4 | length 226.2
  Top w10: C11.1@1440,2214.69 L1.2@1480,2214.69 ; C11.1@1440,2215 1440,2245 1471.42,2276.42 U6.P$4@1471.42,2387.83
  Top w16: C11.1@1440,2214.69 C11.1@1440,2215
N$21: R30.1 U6.P$39 U7.13 | length 1833.2
  Top w10: v1(1580,2815) 1580,2775 1589.53,2764.53 U6.P$39@1589.53,2742.17 ; U7.13@1628.9,1460 1675,1460 v1(1715,1500) v1@1720,1505 ; v1@1720,1505 1744.02,1505 R30.1@1754.02,1515 1730,1515 v1@1720,1505
  Bottom w10: v1(1580,2815) 1730,2815 1770,2775 1770,2585 1850,2505 1850,2305 1800,2255 1800,1585 v1(1715,1500)
N$22: R27.1 U6.P$55 | length 394
  Top w10: R27.1@1249.69,2885 1280,2885 1290,2875 1290,2635 1330.47,2594.53 U6.P$55@1382.83,2594.53
N$23: D7.C R26.2 | length 80.8
  Top w10: D7.C@1129.53,2935 R26.2@1210.31,2935
N$24: D8.C R27.2 | length 80.8
  Top w10: D8.C@1129.53,2885 R27.2@1210.31,2885
N$25: J7.1 JP5.1 | length 200
  Top w24: JP5.1@4560,1205 J7.1@4760,1205
N$26: C10.1 L2.2 U6.P$9 | length 314
  Top w10: U6.P$9@1569.84,2387.83 1569.84,2355.16 1620,2305 1620,2215 C10.1@1620,2214.69 1580.32,2214.69 L2.2@1580,2215
  Top w16: L2.2@1580,2214.69 1580.32,2215 1620,2215 1619.69,2214.69 L2.2@1580.32,2214.69
N$27: D1.A R1.1 | length 287.1
  Top w10: D1.A@2080.47,2505 2080,2504.53 2080,2465 2120,2425 R1.1@2310.31,2425
N$28: C1.1 U1.3 | length 124.9
  Top w10: C1.1@3740,1574.69 3740,1615 3763.15,1638.15 U1.3@3763.15,1690.04
N$29: C2.1 U1.14 | length 117.5
  Top w10: U1.14@3979.69,1690.04 3979.69,1625.32 3985,1620 C2.1@3985,1574.69
N$30: C22.1 U1.37 | length 175.9
  Top w10: U1.37@4274.96,1985.31 4399.69,1985.32 4425,1960 C22.1@4440.31,1960
N$31: C23.1 U1.63 | length 111.9
  Top w10: U1.63@3960,2319.96 3960,2405.31 C23.1@3970,2415.31 3970,2410 C23.1@3965,2405
N$32: J5.1 JP4.1 | length 200
  Top w24: JP4.1@4560,1105 J5.1@4760,1105
N$33: R2.2 U2.P$8 | length 106.2
  Top w10: R2.2@5319.69,2275 5400,2275 5410,2285 5409.13,2285 U2.P$8@5420,2285.87
N$34: R22.2 U6.P$14 | length 186.3
  Top w10: U6.P$14@1668.27,2387.83 1668.27,2336.73 1700,2305 R22.2@1700,2214.69
N$35: C5.1 U1.81 | length 140.6
  Top w10: C5.1@3526.89,2147.8 C5.1@3519.69,2155 3531.89,2142.8 U1.81@3645.04,2142.8
N$36: C6.1 U1.91 | length 134.8
  Top w10: C6.1@3523.74,1950.94 C6.1@3519.69,1955 3580,1955 3589.06,1945.94 U1.91@3645.04,1945.94
N$37: 
N$38: CON1.2 R15.1 | length 115.7
  Top w10: CON1.2@1318.11,1306.5 1401.5,1306.5 1410,1315 R15.1@1430.31,1315
N$39: CON1.3 R33.1 | length 114.3
  Top w10: CON1.3@1318.11,1275 1400,1275 1405,1270 R33.1@1430.31,1270
N$40: D4.A R46.1 | length 68.3
  Top w10: D4.A@1390.47,2065 1390.32,2024.84 R46.1@1410.31,2005
N$41: 
N$42: U4.2 U18.4 | length 439.8
  Top w10: U4.2@3130,1388.82 3130,1425 3140,1435 v1(3260,1435) ; v1(3400,1575) 3405.59,1590.59 U18.4@3423.31,1599.41
  Bottom w10: v1(3260,1435) 3320,1435 3400,1515 v1(3400,1575)
N$43: R47.2 U17.P$8 | length 197.8
  Top w12: U17.P$8@1330.71,1755 1340,1764.29 1350,1775 v1(1360,1775) ; v1(1360,1645) 1360.32,1634.69 R47.2@1360.31,1615
  Bottom w12: v1(1360,1645) v1(1360,1775)
N$44: R35.1 U3.P$5 | length 488.5
  Top w10: R35.1@5319.69,2155 5340,2155 5380,2195 5520,2195 5570,2145 5570,2025 5590,2005 U3.P$5@5642.6,2005
N$45: R42.1 U3.P$8 | length 351.9
  Top w10: R42.1@5319.69,2225 5530,2225 5600,2155 U3.P$8@5642.6,2155
N$46: R43.1 U3.P$1 | length 1071
  Top w10: R43.1@4719.69,1985 4750,1985 4760,1975 5510,1975 5530,1995 5530,2135 5510,2155 U3.P$1@5430,2155
N$47: D9.C U9.6 | length 563.1
  Top w10: D9.C@2139.53,2585 2190,2585 2210,2565 2430,2565 2467.4,2527.6 U9.6@2678.82,2527.6
N$48: R44.1 U3.P$4 | length 731
  Top w10: R44.1@4719.69,2055 4770,2055 4820,2005 U3.P$4@5430,2005
N$49: D9.A R38.1 | length 277.1
  Top w10: D9.A@2080.47,2585 2080,2584.53 2080,2555 2090,2545 2190,2545 2220,2515 R38.1@2310.31,2515
N$50: D10.A R39.1 | length 273.2
  Top w10: D10.A@2080.47,2665 2080,2665 2080,2635 2090,2625 2200,2625 2220,2605 R39.1@2310.31,2605
N$51: L7.P$2 U17.P$7 | length 138.9
  Top w12: U17.P$7@1330.71,1735.31 1359.69,1735.32 1360,1735
  Top w16: 1359.69,1735.32 1370,1735
  Top w24: 1370,1735 1380,1735
  Top w32: 1380,1735 1390,1735 1420,1705 1420,1713.54 L7.P$2@1448.18,1713.54
N$53: R14.2 U12.4 | length 250.7
  Top w10: R14.2@5320,1894.69 5500,1894.69 5517.4,1877.28 U12.4@5517.4,1831.18
N$55: D3.A L6.P$2 U12.1 | length 408
  Top w16: 5430,1735 5436.18,1728.82 U12.1@5442.6,1728.82
  Top w24: D3.A@5195.2,1615 5195.2,1699.8 L6.P$2@5190,1705 5240,1705 5270,1675 5410,1675 5430,1695 5430,1735
N$56: C25.2 R17.2 R45.1 U12.3 | length 505.9
  Top w10: U12.3@5517.4,1728.82 5517.4,1697.6 5540,1675 5700,1675 5720,1695 5720,1795 5710,1805 C25.2@5679.69,1805 R17.2@5679.69,1865 R45.1@5679.69,1915
N$57: 
N$58: 
N$59: D10.C U9.4 | length 565.2
  Top w10: D10.C@2139.53,2665 2410,2665 2472.6,2602.4 U9.4@2678.82,2602.4
OCTW_O: TP4.TP U14.4 U15.P$6 | length 587.5
  Top w10: v1(2820,1915) 2829.37,1925.63 U15.P$6@2872.05,1925.63 ; U14.4@2857.4,1487.6 U14.4@2857.4,1491.18
  Top w12: v1(2820,1505) 2830,1495 2853.58,1495 U14.4@2857.4,1491.18 2916.18,1491.18 TP4.TP@2910,1505
  Bottom w10: v1(2820,1505) v1(2820,1915)
PWREN#: U6.P$60
RESET#: C39.1 J2.5 J6.5 R6.1 S2.P$3 S2.P$4 TP18.TP U1.11 | length 6146.7
  Top w10: J2.5@2660,2905 2730,2975 3000,2975 v1(3010,2965) 3020,2975 3580,2975 ; R6.1@2979.69,2585 v1(3310,2585) ; v1(3430,1335) 3440,1325 3460,1305 3600,1305 3613,1282 S2.P$3@3630,1282 ; v1(3430,1475) 3450,1465 3840,1465 3870,1495 3870,1565 3880,1575 3880.32,1574.69 C39.1@3895,1574.69 3895,1590 3920.63,1615.63 U1.11@3920.63,1690.04 ; TP18.TP@3580,2945 3580,2975 ; J6.5@5160,2905 5090,2975 3580,2975
  Top w16: S2.P$3@3630,1282 S2.P$4@3989,1282
  Bottom w10: v1(3010,2965) 3010,2755 3060,2705 3250,2705 3310,2645 v1(3310,2585) 3310,2005 3430,1885 v1(3430,1475) ; v1(3430,1335) v1(3430,1475) ; 3430,1435 v1(3430,1475)
S$1:  | length 2080
  Top w10: 3800,2755 3800,2955 4640,2955 4640,2755 3800,2755
S$2:  | length 113.1
  Top w10: 3830,2795 3910,2875
SCI_RX: R16.2 TP25.TP U5.11 U10.P$13 | length 977.9
  Top w10: R16.2@1865.98,1715 1910,1715 1930,1735 1930,1835 1945,1850 U5.11@1991.1,1850 2180,1850 ; TP25.TP@2190,1825 2170,1845 2175,1845 2180,1850 ; U10.P$13@2630.32,1708.23 2536.77,1708.23 2395,1850 2180,1850
SCI_TX: R30.2 TP26.TP U7.4 U10.P$3 | length 814.5
  Top w10: R30.2@1865.98,1515 1890,1515 1945,1460 U7.4@1991.1,1460 2155,1460 2200,1505 2200,1715 TP26.TP@2205,1720 ; TP26.TP@2190,1735 TP26.TP@2205,1720 ; U10.P$3@2400,1733.82 2218.82,1733.82 TP26.TP@2205,1720
SUSPEND#: U6.P$36
TCK: R20.2 U1.67 U5.14 | length 2641
  Top w10: R20.2@1865.98,2015 1920,2015 1935,2000 U5.14@1991.1,2000 2175,2000 2230,2055 v1(3340,2055) ; v1(3340,2495) 3850,2495 3881.26,2463.74 U1.67@3881.26,2319.96
  Bottom w10: v1(3340,2055) v1(3340,2495)
TDI: R19.2 U1.71 U5.13 | length 2560.2
  Top w10: R19.2@1865.98,1915 1910,1915 1945,1950 U5.13@1991.1,1950 2085,1950 v1(2090,1955) ; v1(2200,2485) 2900,2485 2940,2445 3050,2445 3090,2405 3530,2405 3560,2435 3770,2435 3802.52,2402.48 U1.71@3802.52,2319.96
  Bottom w10: v1(2090,1955) 2110,1975 2110,2395 v1(2200,2485)
TDO: R9.2 R32.2 S1.2 U1.70 U7.3 | length 3445.1
  Top w10: R32.2@1865.98,1415 1986.1,1415 U7.3@1991.1,1410 2175,1410 2310,1545 2880,1545 2940,1605 v1(3240,1605) ; S1.2@2819.29,2275 R9.2@2940.31,2275 2940.32,2295.31 2950,2305 v1(3270,2305) ; v1(3270,2435) 3530,2435 3550,2455 3780,2455 3822.2,2412.8 U1.70@3822.2,2319.96
  Bottom w10: v1(3240,1605) 3240,1735 3270,1765 v1(3270,2305) v1(3270,2435)
TMS: R18.2 U1.72 U5.12 | length 2572.1
  Top w10: R18.2@1865.98,1815 1920,1869.02 1920,1875 1945,1900 U5.12@1991.1,1900 2125,1900 v1(2140,1915) ; v1(2230,2455) 2900,2455 2930,2425 3040,2425 3080,2385 3540,2385 3570,2415 3760,2415 3782.83,2392.17 U1.72@3782.83,2319.96
  Bottom w10: v1(2140,1915) 2140,2365 v1(2230,2455)
TRST: R10.2 S1.3 U1.12 | length 1995.5
  Top w10: S1.3@2819.29,2375 v1(2910,2375) R10.2@2940.31,2375 ; v1(2910,1745) 3070,1745 3090,1765 3400,1765 3480,1685 3640,1685 3770,1815 3930,1815 3940.32,1804.69 U1.12@3940.31,1690.04
  Bottom w10: v1(2910,1745) v1(2910,2375)
USBVCC: C44.2 F1.1 U17.P$2 U17.P$3 | length 263
  Top w12: C44.2@1120,1722.01 1126.38,1715.63 U17.P$3@1248.03,1715.63 ; C44.2@1120,1725 1130,1735 1140,1735 1140.32,1735.32 U17.P$2@1248.03,1735.31
VDDA: C19.1 L3.1 TP19.TP U1.25 | length 374.2
  Top w10: U1.25@4196.22,1690.04 4204.96,1690.04 4210,1685 ; 4205.04,1699.96 4210,1695
  Top w16: 4210,1695 4210,1685 4210,1655 4250,1615 C19.1@4250,1584.69 L3.1@4290,1584.69 v1(4290,1615) 4290,1655 v1(4300,1665) TP19.TP@4400,1665
VDDIO: C20.1 C26.1 C27.1 C28.1 C29.1 C30.1 L4.1 U1.5 U1.13 U1.38 U1.61 U1.79 U1.93 | length 3140.4
  Top w10: v1(3550,1905) 3551.57,1906.57 U1.93@3645.04,1906.57 ; v1(3550,2205) 3570,2205 3592.83,2182.17 U1.79@3645.04,2182.17 ; v1@3558.11,1911.57 3557.49,1912.21 3550,1920 3530,1920 C30.1@3519.69,1915 C30.1@3520,1915 ; C20.1@3800,1574.69 3800,1585 3807.52,1592.52 ; v1(3800,1605) 3802.52,1607.52 U1.5@3802.52,1690.04 ; v1(3950,1605) 3960,1615 U1.13@3960,1690.04 ; v1(4000,2240) 3999.37,2240.63 U1.61@3999.37,2319.96 3999.37,2409.69 C28.1@4005,2415.31 C28.1@4004.37,2414.69 ; v1(4220,2015) 4225.98,2009.02 4230,2005 U1.38@4274.96,2005 4410,2005 4415,2000 C27.1@4440.31,2000 ; C30.1@3520,1915 3520.15,1914.85 3525,1910 3530,1910 3527.61,1912.39 3525,1915 C30.1@3520,1915
  Top w16: C30.1@3519.69,1915 3520.15,1914.85 3527.61,1912.39 v1(3550,1905) 3536.57,1911.57 ; C29.1@3519.69,2205 L4.1@3519.69,2255 ; C29.1@3520,2205 v1(3550,2205) v1(3550,2235) ; v1(3800,1605) 3807.52,1597.48 3807.52,1592.52 ; C26.1@3940,1574.69 3940,1595 v1(3950,1605)
  VDD w16: v1@3546.57,1911.57 v1(3550,1905)
  VDD w24: v1@3546.57,1911.57 3546.57,1991.57 3570,2015 3570,2025 ; v1(3550,1905) 3550,1885 3620,1815 3630,1815 3790,1655 3790,1615 v1(3800,1605) 3810,1595 3940,1595 v1(3950,1605) ; v1(4000,2240) 3995,2240 3950,2195 3740,2195 3690,2245 3560,2245 v1(3550,2235) v1(3550,2205) 3550,2195 3570,2175 3570,2025 ; v1(4220,2015) 3580,2015 3570,2025
XUSB: CON1.1@1318.11,1337.99 F1.2 | length 482.9
  Top w10: F1.2@1236.77,1585 1236.77,1577.32 F1.2@1239.05,1575.05
  Top w16: CON1.1@1318.11,1337.99 1318.11,1343.11 CON1.1@1320,1345
  Top w32: F1.2@1230,1585 1239.05,1575.05 1280,1530 1390,1530 1420,1500 1420,1375 1390,1345 CON1.1@1320,1345
pads on no net: C55.1@160,1400 C55.1@3615,1290 C55.2@160,1020 C55.2@3805,1290 CON1.1@1200,1188.39 CON1.1@1200,1361.61 CON1.4 CON1.M1 CON1.M2 CON1.M3 CON1.M4 J2.4 J3.10 J4.8 J5.2 J5.6 J6.4 J7.10 J8.7 J8.8 U1.24 U1.45 U5.7 U6.P$22 U6.P$23 U6.P$24 U6.P$26 U6.P$27 U6.P$28 U6.P$29 U6.P$30 U6.P$33 U6.P$34 U6.P$43 U6.P$44 U6.P$45 U6.P$46 U6.P$48 U6.P$52 U6.P$53 U6.P$57 U6.P$58 U6.P$59 U7.6 U7.11 U10.P$1 U10.P$12 U16.P$2 U16.P$4 U18.1
copper on no net: | length 366.4
  Top w10: 3933.31,2830 ccw(c3875,2830) 3933.31,2830

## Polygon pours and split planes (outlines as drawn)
no net on tDocu (solid): 2645,1180 2665,1180 2665,1197.07 2697.07,1165 2665,1132.93 2665,1150 2645,1150
GND on GND "GND-GND" (solid, remove dead copper, pour order 0): 1885,2990 1885,1009.97 5855,1030.03 5855,1603.49 5872.68,1630 6122.07,1630 6135,1642.93 6135,2990
AGND on GND "GND-AGND" (solid, remove dead copper, pour order 24): 1014.96,2990 1835,2990 1835,1010 1407.93,1010 1395,1022.93 1395,1474.19 1386.4,1500 1317.93,1500 1295,1522.93 1295,1632.93 1267.93,1660 1025.04,1660
GND on Top "Top-GND" (solid, remove dead copper, pour order 2): 5085,1930 5085,1837.07 5112.07,1810 5272.07,1810 5292.07,1790 5357.93,1790 5367.93,1800 5537.93,1800 5555,1817.07 5555,1947.07 5567.93,1960 5655,1960 5655,1920 5635,1920 5635,1902.93 5622.07,1890 5612.07,1890 5605,1882.93 5605,1787.07 5622.07,1770 5695,1770 5695,1712.93 5682.07,1700 5597.93,1700 5537.93,1760 5502.07,1760 5480,1737.93 5457.93,1760 5412.07,1760 5405,1752.93 5405,1700 5287.93,1700 5237.93,1750 5132.07,1750 5105,1722.93 5105,1545 4885,1545 4885,1930
GND on Top "Top-GND 1" (solid, remove dead copper, pour order 4): 4277.93,2440 4517.93,2200 5002.07,2200 5045,2242.93 5045,2430 4932.07,2430 4852.07,2510 4697.93,2510 4747.93,2460 4807.93,2460 4825,2442.93 4825,2382.93 4865,2342.93 4865,2277.07 4837.93,2250 4612.07,2250 4575,2287.07 4575,2342.93 4605,2372.93 4605,2440
GND on Top "Top-GND 2" (solid, remove dead copper, pour order 6): 2315,1380 2027.93,1380 2015,1367.07 2015,1352.93 2037.93,1330 2077.93,1330 2095,1312.93 2095,1297.07 2067.93,1270 1942.07,1270 1925,1287.07 1925,1350 1897.93,1350 1855,1307.07 1855,1297.07 1835,1277.07 1835,1262.93 1897.93,1200 1977.93,1200 2007.93,1170 2135,1170 2135,1310 2315,1310
GND on Top "Top-GND 3" (solid, remove dead copper, pour order 8): 3695,2257.07 3695,1762.93 3727.93,1730 4211.67,1730 4255,1762.5 4255,1777.07 4235,1797.07 4235,2257.07 4202.07,2290 3727.93,2290
+3V3 on Top "Top-+3V3" (solid, remove dead copper, pour order 10): 2062.07,2310 1917.93,2310 1885,2277.07 1885,2112.93 1897.93,2100 2062.07,2100 2075,2112.93 2075,2297.07
+3V3 on Top "Top-+3V3 1" (solid, remove dead copper, pour order 12): 2200,1150 1992.07,1150 1972.07,1170 1887.93,1170 1865,1147.07 1865,1042.93 1887.93,1020 2272.07,1020 2305,1052.93 2305,1127.07 2282.07,1150
+3V3 on Top "Top-+3V3 2" (solid, remove dead copper, pour order 16): 5105,1930 5105,1852.93 5137.93,1820 5297.93,1820 5307.93,1810 5352.07,1810 5372.07,1830 5417.93,1830 5437.93,1810 5452.07,1810 5465,1822.93 5465,1870 5265,1870 5265,1930
USBVCC on Top "Top-USBVCC" (solid, remove dead copper, pour order 18): 1215,1740 1202.07,1740 1192.07,1750 1057.93,1750 1035,1727.07 1035,1522.93 1047.93,1510 1132.07,1510 1155,1532.93 1155,1652.93 1215,1712.93
AGND on Top "Top-AGND" (solid, remove dead copper, pour order 20): 1046.46,1888.54 1057.93,1900 1252.07,1900 1263.54,1888.54 1275,1877.07 1275,1807.07 1285,1797.07 1285,1772.93 1272.07,1760 1047.93,1760 1035,1772.93 1035,1877.07
AGND on Top "Top-AGND 1" (solid, remove dead copper, pour order 22): 1415,2710 1692.07,2710 1705,2697.07 1705,2522.93 1675,2492.93 1675,2467.07 1695,2447.07 1695,2420 1415,2420
FTDI_3V3 on Top "Top-FTDI_3V3" (solid, remove dead copper, pour order 26): 1425,1980 1307.93,1980 1295,1967.07 1295,1832.93 1317.93,1810 1462.07,1810 1485,1832.93 1485,1920 1425,1920
FTDI_3V3 on Top "Top-FTDI_3V3 1" (solid, remove dead copper, pour order 28): 1585,1307.07 1585,1112.93 1597.93,1100 1667.93,1100 1717.93,1050 1845,1050 1845,1195 1845,1207.07 1822.07,1230 1702.07,1230 1695,1237.07 1695,1297.07 1672.07,1320 1597.93,1320
FTDI_3V3 on Top "Top-FTDI_3V3 2" (solid, remove dead copper, pour order 32): 1725,2280 1725,2187.07 1717.93,2180 1695,2180 1695,2102.93 1707.93,2090 1785,2090 1785,2280
VDDIO on Top "Top-VDDIO" (solid, remove dead copper, pour order 36): 3515,2260 3515,2190 3585,2190 3585,2227.07 3552.07,2260
+3V3 on VDD "VDD-+3V3" (solid, remove dead copper, pour order 14): 1885,1042.93 1885,2957.07 1927.94,3000.01 3960,2990 4819.96,2990 6125,3000.04 6125,2790 5842.18,2790 5595,2523.04 5595,1360.04 4420.02,1350 3462.07,1350 3402.07,1290 3317.93,1290 3257.93,1350 2152.07,1350 2145,1342.93 2145,1157.07 2172.07,1130 2317.93,1130 2337.93,1150 3192.07,1150 3212.07,1130 3437.93,1130 3477.95,1170.02 4602.09,1159.98 4625,1137.07 4625,1020 1907.93,1020
FTDI_3V3 on VDD "VDD-FTDI_3V3" (solid, remove dead copper, pour order 30): 1035,2970 1035,1732.93 1047.93,1720 1327.93,1720 1435,1612.93 1435,1437.07 1355,1357.07 1355,1142.93 1457.93,1040 1822.07,1040 1835,1052.93 1835,2970
+5V on VDD "VDD-+5V" (solid, remove dead copper, pour order 34): 2165,1320 2165,1182.93 2197.93,1150 2302.4,1150 2342.4,1200 3187.93,1200 3237.93,1150 3402.07,1150 3452.07,1200 4608.49,1200 4635,1182.32 4635,1052.93 4657.93,1030 5815,1030 5815,2122.93 5852.07,2160 5867.93,2160 5885,2142.93 5885,1592.93 5927.93,1550 6082.07,1550 6125,1592.93 6125,2737.07 6102.07,2760 5847.8,2760 5625,2516.94 5625,1320.02 3477.94,1330.01 3417.93,1270 3312.07,1270 3262.07,1320

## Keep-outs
Bottom:
  rectangle: 1870,2525 1970,2625
Keep-Out Layer:
  the board outline again, w10

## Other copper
Top:
  text "94V-0" at 4000,2939.19 h34 r180
  text "For evaluation only;" at 4625,2898.52 h34 r180
  text "Pb" at 3915,2865.24 h42.5 r180
  text "not FCC approved" at 4625,2864.52 h34 r180
  text "for resale." at 4625,2819.19 h34 r180

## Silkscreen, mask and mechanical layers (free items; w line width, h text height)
Top Overlay:
  rectangle: 1850,2155 1890,2845
  rectangle: 1850,1165 1890,1255
  lines w6: 2910,1865 2940,1915 ; 2920,1905 2940,1915 ; 2940,1895 2940,1915
  text "20" at 2270,2955 h49.6 r90
  text "19" at 2370,2955 h49.6 r90
  text "18" at 2470,2955 h49.6 r90
  text "17" at 2580,2955 h49.6 r90
  text "16" at 2670,2955 h49.6 r90
  text "15" at 2770,2955 h49.6 r90
  text "14" at 2870,2955 h49.6 r90
  text "13" at 2970,2955 h49.6 r90
  text "12" at 3070,2955 h49.6 r90
  text "11" at 3180,2955 h49.6 r90
  text "60" at 4770,2955 h49.6 r90
  text "59" at 4870,2955 h49.6 r90
  text "58" at 4970,2955 h49.6 r90
  text "57" at 5080,2955 h49.6 r90
  text "56" at 5170,2955 h49.6 r90
  text "55" at 5270,2955 h49.6 r90
  text "54" at 5370,2955 h49.6 r90
  text "53" at 5470,2955 h49.6 r90
  text "52" at 5570,2955 h49.6 r90
  text "51" at 5680,2955 h49.6 r90
  text "Reset" at 3620,2895 h49.6
  text "3V3" at 6070,2775 h49.6 r90
  text "GND" at 5870,2755 h49.6 r90
  text "GND" at 5970,2755 h49.6 r90
  text "GND" at 1920,2715 h49.6
  text "40" at 2280,2705 h49.6 r90
  text "39" at 2380,2705 h49.6 r90
  text "38" at 2480,2705 h49.6 r90
  text "37" at 2580,2705 h49.6 r90
  text "36" at 2680,2705 h49.6 r90
  text "35" at 2780,2705 h49.6 r90
  text "34" at 2880,2705 h49.6 r90
  text "31" at 3180,2705 h49.6 r90
  text "80" at 4780,2705 h49.6 r90
  text "79" at 4880,2705 h49.6 r90
  text "78" at 4980,2705 h49.6 r90
  text "77" at 5080,2705 h49.6 r90
  text "76" at 5180,2705 h49.6 r90
  text "75" at 5280,2705 h49.6 r90
  text "74" at 5380,2705 h49.6 r90
  text "73" at 5480,2705 h49.6 r90
  text "72" at 5580,2705 h49.6 r90
  text "71" at 5680,2705 h49.6 r90
  text "33" at 2980,2700 h49.6 r90
  text "32" at 3080,2700 h49.6 r90
  text "GND" at 4970,2405 h49.6
  text "XDS100v2" at 1835,2385 h42.5 r90
  text "+3V3" at 1980,2295 h49.6
  text "GND" at 2120,2145 h49.6
  text "Boot" at 2570,2035 h42.5
  text "GND" at 4995,1935 h49.6
  text "CH_SEL" at 3270,1930 h34
  text "MUX_SEL" at 3270,1805 h34
  text "VDDA" at 4340,1605 h49.6
  text "TMS320F28069M" at 4940,1605 h77.5 r90
  text "VER:1.1" at 5030,1605 h77.5 r90
  text "+3V3" at 4420,1495 h49.6
  text "+5V" at 5620,1425 h49.6
  text "CAN" at 6010,1415 h49.6
  text "+5V" at 2320,1385 h49.6
  text "CAN-H" at 5860,1295 h27.2
  text "22" at 2370,1265 h49.6 r90
  text "23" at 2470,1265 h49.6 r90
  text "24" at 2570,1265 h49.6 r90
  text "25" at 2670,1265 h49.6 r90
  text "26" at 2770,1265 h49.6 r90
  text "27" at 2870,1265 h49.6 r90
  text "28" at 2970,1265 h49.6 r90
  text "29" at 3070,1265 h49.6 r90
  text "30" at 3170,1265 h49.6 r90
  text "62" at 4870,1265 h49.6 r90
  text "63" at 4970,1265 h49.6 r90
  text "64" at 5070,1265 h49.6 r90
  text "65" at 5170,1265 h49.6 r90
  text "66" at 5270,1265 h49.6 r90
  text "67" at 5370,1265 h49.6 r90
  text "68" at 5470,1265 h49.6 r90
  text "69" at 5570,1265 h49.6 r90
  text "70" at 5680,1265 h49.6 r90
  text "CAN-L" at 5860,1195 h27.2
  text "+3V3" at 2030,1115 h49.6
  text "Reset" at 4080,1075 h34 r90
  text "3V3" at 1640,1045 h49.6
  text "GND" at 5720,1025 h49.6
  text "PGND" at 5840,1025 h49.6
  text "1" at 2280,1015 h49.6 r90
  text "2" at 2380,1015 h49.6 r90
  text "3" at 2480,1015 h49.6 r90
  text "4" at 2580,1015 h49.6 r90
  text "5" at 2680,1015 h49.6 r90
  text "6" at 2780,1015 h49.6 r90
  text "7" at 2880,1015 h49.6 r90
  text "8" at 2980,1015 h49.6 r90
  text "9" at 3090,1015 h49.6 r90
  text "10" at 3180,1005 h49.6 r90
  text "41" at 4780,1005 h49.6 r90
  text "42" at 4880,1005 h49.6 r90
  text "43" at 4980,1005 h49.6 r90
  text "44" at 5080,1005 h49.6 r90
  text "45" at 5180,1005 h49.6 r90
  text "46" at 5280,1005 h49.6 r90
  text "47" at 5380,1005 h49.6 r90
  text "48" at 5480,1005 h49.6 r90
  text "49" at 5590,1005 h49.6 r90
  text "50" at 5680,1005 h49.6 r90
Top Solder:
  rectangle: 1420,1855 1480,1905
Dimension:
  the board outline again, w10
